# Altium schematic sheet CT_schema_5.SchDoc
size 266 x 267 mm
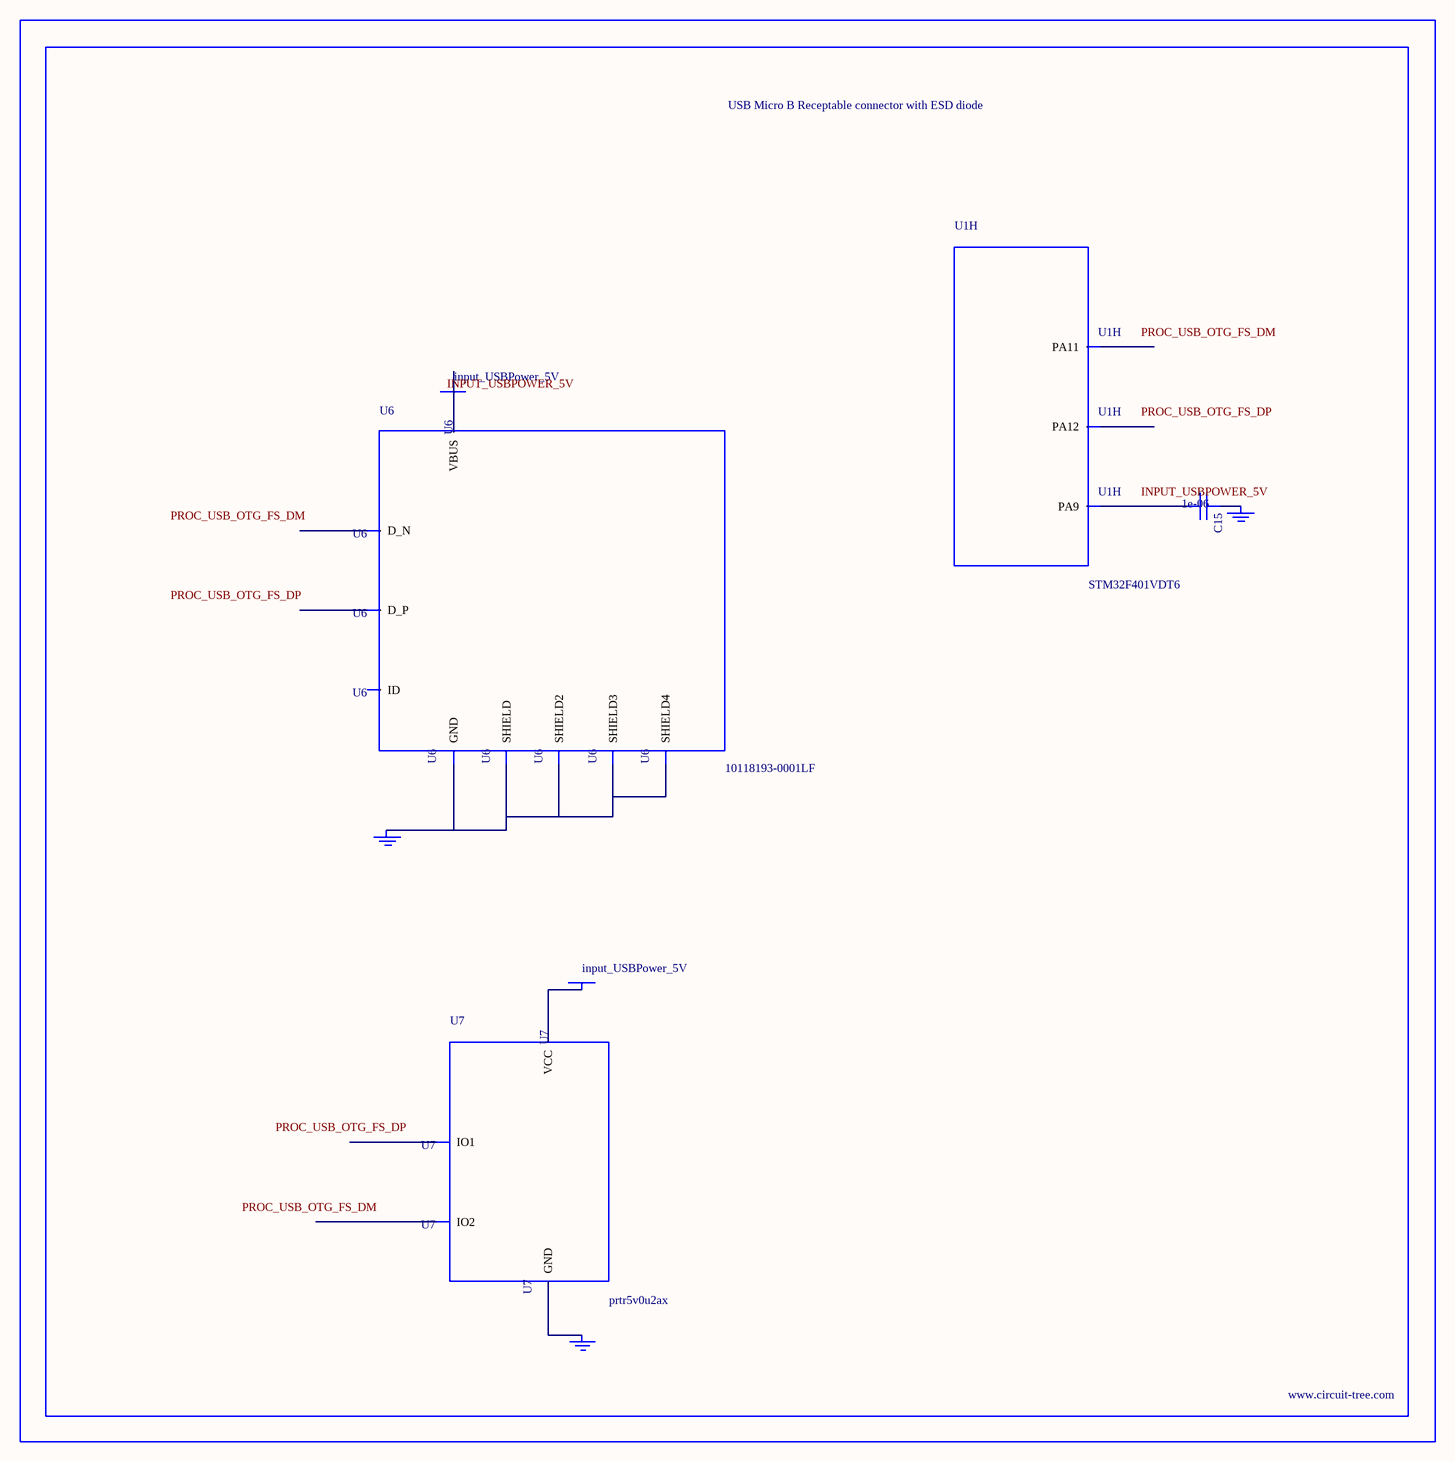
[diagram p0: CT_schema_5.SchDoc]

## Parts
BORDER4  (no value)
C15  1e-06  [C0603]
GND_INSTANCE_4_0  (no value)
GND_INSTANCE_4_1  (no value)
GND_INSTANCE_4_2  (no value)
POWER_INSTANCE_4_0  input_USBPower_5V
POWER_INSTANCE_4_1  input_USBPower_5V
U1  STM32F401VDT6  [LQFP100]  (part H of 10)
U6  10118193-0001LF  [FCI_10118193-0001LF]
U7  prtr5v0u2ax  [SOT143B]

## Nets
NetC15_1: C15.1 GND_INSTANCE_4_1.0(GND)
NetC15_2: C15.2 U1.68(PA9)
NetGND_INSTANCE_4_0_0: GND_INSTANCE_4_0.0(GND) U6.5(GND) U6.6(SHIELD) U6.7(SHIELD2) U6.8(SHIELD3) U6.9(SHIELD4)
NetGND_INSTANCE_4_2_0: GND_INSTANCE_4_2.0(GND) U7.1(GND)
NetPOWER_INSTANCE_4_0_0: POWER_INSTANCE_4_0.0(PWR) U6.1(VBUS)
NetPOWER_INSTANCE_4_1_0: POWER_INSTANCE_4_1.0(PWR) U7.4(VCC)

Not connected (* = marked no-connect by the designer): U1 70(PA11) 71(PA12); U6 2(D_N) 3(D_P) 4(ID); U7 2(IO1) 3(IO2)

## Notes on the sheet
- Labels drawn without touching a wire or pin: INPUT_USBPOWER_5V, PROC_USB_OTG_FS_DM, PROC_USB_OTG_FS_DP

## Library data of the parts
BORDER4 = BORDER_PAGE4
C15 = C0603C105K3RACTU
GND_INSTANCE_4_0-GND_INSTANCE_4_2 = GND
POWER_INSTANCE_4_0 POWER_INSTANCE_4_1 = PWR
